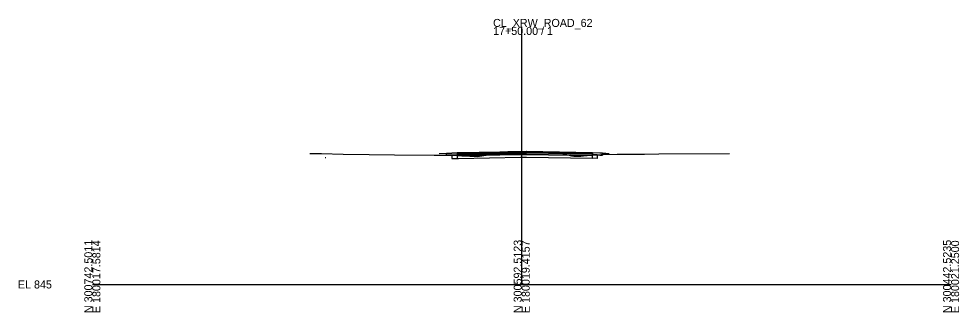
# Model space of a CAD drawing. Extents: x -26 to 303, y 490 to 4093.
# Drawn here: x -25.7 to 302.8, y 2490.3 to 2592.8 of the extents above; entities that cross this region are included whole.
import ezdxf

# ---------------------------------------------------------------- set-up
doc = ezdxf.new("R2010")
doc.units = 0
for name, color, linetype in [('CL_P_Construction', 7, 'Continuous'), ('CM_Corridor_Bottom_Mesh', 7, 'Continuous'), ('CM_Corridor_Top_Mesh', 7, 'Continuous'), ('Default', 7, 'Continuous'), ('DT_P_TIN_Hull', 7, 'Continuous'), ('GK_Cells', 7, 'Continuous'), ('MD_P_Subgrade', 7, 'Continuous'), ('MD_P_Surface_Aggregate_Base', 7, 'Continuous'), ('MD_P_Surface_Asphalt_Concrete_Base', 7, 'Continuous'), ('MD_P_Surface_Asphalt_Concrete_Surface_Course', 7, 'Continuous'), ('MD_P_Surface_Chemically_Stabalized_Subgrade', 7, 'Continuous'), ('MD_P_Surface_Finished_Grade', 7, 'Continuous'), ('SV_X_Text_Comment', 7, 'Continuous'), ('VG_X_Text', 7, 'Continuous'), ('XS_X_Ground_Line', 7, 'Continuous')]:
    doc.layers.add(name, color=color, linetype=linetype)

msp = doc.modelspace()

# ---------------------------------------------------------------- linework, layer by layer
at = {"layer": 'CM_Corridor_Bottom_Mesh'}
for points in [[(127.46, 2546), (127.46, 2545.33), (125.58, 2545.23), (123.69, 2545.13), (123.69, 2545.8), (121.18, 2545.62)], [(180.59, 2545.66), (178.19, 2545.84), (178.19, 2545.17), (177.31, 2545.22), (176.42, 2545.27), (174.69, 2545.37), (174.69, 2546.04)]]:
    msp.add_lwpolyline(points, dxfattribs=at)
at = {"layer": 'CM_Corridor_Top_Mesh'}
for points in [[(127.46, 2546), (123.69, 2545.8), (121.18, 2545.62)], [(180.59, 2545.66), (178.19, 2545.84), (177.31, 2545.89), (174.69, 2546.04)]]:
    msp.add_lwpolyline(points, dxfattribs=at)
at = {"layer": 'DT_P_TIN_Hull'}
msp.add_lwpolyline([(127.46, 2546), (127.91, 2546.01), (149.53, 2546.37), (151.5, 2546.41), (151.56, 2546.41), (151.57, 2546.41), (151.6, 2546.41), (151.62, 2546.41), (151.64, 2546.41), (151.72, 2546.41), (174.69, 2546.04)], dxfattribs=at)
at = {"layer": 'GK_Cells'}
for p, q in [((150, 2500), (150, 2590)), ((0, 2500), (150, 2500)), ((150, 2500), (300, 2500))]:
    msp.add_line(p, q, dxfattribs=at)
at = {"layer": 'MD_P_Subgrade'}
for points in [[(123.69, 2545.13), (123.69, 2545.8)], [(123.69, 2545.13), (125.58, 2545.23), (125.58, 2543.99), (127.46, 2544.06)], [(178.19, 2545.17), (177.31, 2545.22), (176.42, 2545.27), (176.42, 2544.03), (174.69, 2544.1)], [(178.19, 2545.17), (178.19, 2545.84)]]:
    msp.add_lwpolyline(points, dxfattribs=at)
at = {"layer": 'MD_P_Surface_Aggregate_Base'}
for points in [[(127.46, 2546), (127.46, 2545.33), (123.69, 2545.13), (123.69, 2545.8), (127.46, 2546)], [(151.6, 2545.97), (151.57, 2545.97), (151.56, 2545.97), (151.5, 2545.97), (149.53, 2545.94), (127.91, 2545.57), (127.46, 2545.56), (127.46, 2545.06), (127.91, 2545.07), (149.53, 2545.44), (151.5, 2545.47), (151.56, 2545.47), (151.57, 2545.47), (151.6, 2545.47), (151.62, 2545.47), (151.64, 2545.47), (151.72, 2545.47), (174.69, 2545.1), (174.69, 2545.6), (151.72, 2545.97), (151.64, 2545.97), (151.62, 2545.97), (151.6, 2545.97)], [(177.31, 2545.89), (174.69, 2546.04), (174.69, 2545.37), (177.31, 2545.22), (178.19, 2545.17), (178.19, 2545.84), (177.31, 2545.89)]]:
    msp.add_lwpolyline(points, dxfattribs=at)
at = {"layer": 'MD_P_Surface_Asphalt_Concrete_Base'}
msp.add_lwpolyline([(151.6, 2546.3), (151.57, 2546.3), (151.56, 2546.3), (151.5, 2546.3), (149.53, 2546.27), (127.91, 2545.9), (127.46, 2545.9), (127.46, 2545.56), (127.91, 2545.57), (149.53, 2545.94), (151.5, 2545.97), (151.56, 2545.97), (151.57, 2545.97), (151.6, 2545.97), (151.62, 2545.97), (151.64, 2545.97), (151.72, 2545.97), (174.69, 2545.6), (174.69, 2545.94), (151.72, 2546.3), (151.64, 2546.3), (151.62, 2546.3), (151.6, 2546.3)], dxfattribs=at)
at = {"layer": 'MD_P_Surface_Asphalt_Concrete_Surface_Course'}
msp.add_lwpolyline([(151.6, 2546.41), (151.57, 2546.41), (151.56, 2546.41), (151.5, 2546.41), (149.53, 2546.37), (127.91, 2546.01), (127.46, 2546), (127.46, 2545.9), (127.91, 2545.9), (149.53, 2546.27), (151.5, 2546.3), (151.56, 2546.3), (151.57, 2546.3), (151.6, 2546.3), (151.62, 2546.3), (151.64, 2546.3), (151.72, 2546.3), (174.69, 2545.94), (174.69, 2546.04), (151.72, 2546.41), (151.64, 2546.41), (151.62, 2546.41), (151.6, 2546.41)], dxfattribs=at)
at = {"layer": 'MD_P_Surface_Chemically_Stabalized_Subgrade'}
msp.add_lwpolyline([(151.6, 2545.47), (151.57, 2545.47), (151.56, 2545.47), (151.5, 2545.47), (149.53, 2545.44), (127.91, 2545.07), (127.46, 2545.06), (127.46, 2544.06), (127.91, 2544.07), (149.53, 2544.44), (151.5, 2544.47), (151.56, 2544.47), (151.57, 2544.47), (151.6, 2544.47), (151.62, 2544.47), (151.64, 2544.47), (151.72, 2544.47), (174.69, 2544.1), (174.69, 2545.1), (151.72, 2545.47), (151.64, 2545.47), (151.62, 2545.47), (151.6, 2545.47)], dxfattribs=at)
at = {"layer": 'MD_P_Surface_Finished_Grade'}
for points in [[(123.69, 2545.8), (121.18, 2545.62)], [(178.19, 2545.84), (180.59, 2545.66)]]:
    msp.add_lwpolyline(points, dxfattribs=at)
at = {"layer": 'SV_X_Text_Comment'}
msp.add_lwpolyline([(81.57, 2544.23), (81.45, 2544.23)], dxfattribs=at)
at = {"layer": 'VG_X_Text'}
msp.add_lwpolyline([(81.45, 2544.23), (81.33, 2544.23)], dxfattribs=at)
msp.add_lwpolyline([(81.45, 2544.23), (81.33, 2544.23)], dxfattribs=at)
at = {"layer": 'XS_X_Ground_Line'}
msp.add_lwpolyline([(75.93, 2545.75), (80.08, 2545.74), (87.57, 2545.54), (96.69, 2545.42), (105.58, 2545.28), (119.4, 2545.21), (126.67, 2545.15), (129.05, 2545), (134.58, 2544.7), (136.78, 2545.04), (140.21, 2545.57), (141.19, 2545.78), (143.59, 2546.17), (144.67, 2546.32), (145.17, 2546.44), (146.32, 2546.47), (147.08, 2546.48), (151.64, 2546.49), (154.19, 2546.51), (158.71, 2546.31), (160.87, 2546.22), (161.46, 2546.21), (162.82, 2546.19), (164.76, 2545.66), (165.6, 2545.43), (167.43, 2545.01), (168.22, 2544.82), (170.62, 2544.89), (171.55, 2544.92), (174.24, 2545.15), (177.8, 2545.43), (183.36, 2545.51), (192.91, 2545.58), (197.9, 2545.6), (222.58, 2545.81)], dxfattribs=at)

# ---------------------------------------------------------------- texts
at = {"layer": 'CL_P_Construction'}
msp.add_text('X', height=0.1, dxfattribs=at).set_placement((151.57, 2546.36))
at = {"layer": 'Default'}
msp.add_text('-', height=0.0001, dxfattribs=at).set_placement((0, 2500))
at = {"layer": 'GK_Cells'}
for s, p in [('CL_XRW_ROAD_62', (140, 2590)), ('17+50.00 / 1', (140, 2587.2)), ('EL 845', (-26, 2498.6))]:
    msp.add_text(s, height=2.8, dxfattribs=at).set_placement(p)
for s, p in [('N 300742.5011', (0, 2490)), ('E 180017.5814', (2.8, 2490)), ('N 300592.5123', (150, 2490)), ('E 180019.4157', (152.8, 2490)), ('N 300442.5235', (300, 2490)), ('E 180021.2500', (302.8, 2490))]:
    msp.add_text(s, height=2.8, rotation=90, dxfattribs=at).set_placement(p)

doc.saveas('drawing.dxf')
